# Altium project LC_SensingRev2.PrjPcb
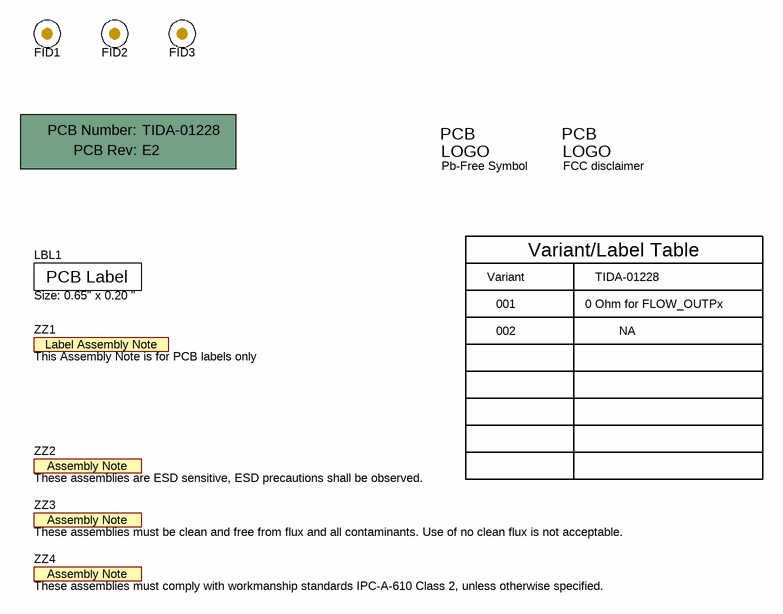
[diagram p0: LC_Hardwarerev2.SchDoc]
CopyrightYear: 2017; EVM_Orderable: NA; PCB_Layout: a0797195; PCB_Rev: E2; PRJ_Customer: Public Release; PRJ_Engineer: a0797195; PRJ_Number: TIDA-01228; PRJ_Title: LC Rotation Detection; SCH_Rev: E2; TechSupport: http://www.ti.com/support; TID: TIDA-01228
2 sheets, 61 parts. Net scope: global (net labels, ports and power ports of the same name join across sheets).
Board file: LC_Sensingrev2.PcbDoc
Sheets:
  LC_Hardwarerev2.SchDoc
  LC_PMOSrev2.SchDoc

## Sheet LC_Hardwarerev2.SchDoc
size A4; Date: Not shown in title block; ApprovedBy: Not shown in title block; CheckedBy: Not shown in title block; Author: Not shown in title block; CompanyName: Not shown in title block; DrawnBy: a0797195; Engineer: Not shown in title block; Organization: Not shown in title block; Address1: Not shown in title block; Address2: Not shown in title block; Address3: Not shown in title block; Address4: Not shown in title block; DocumentNumber: 1; Revision: Use project parameter SCH_Rev; SheetNumber: 2; SheetTotal: 2; PageSetup: Record=PageOptions¦CenterHorizontal=True¦CenterVertical=True¦PrintScale=1.00¦XCorrection=1.00¦YCorrection=1.00¦PrintKind=0¦BorderSize=5000000¦LeftOffset=0¦BottomOffset=0¦Orientation=2¦PaperLength=1000¦PaperWidth=1000¦Scale=100¦PaperSource=15¦PrintQuality=600¦MediaType=1¦DitherType=10¦PaperKind=Letter¦PrintScaleMode=1; EVM_orderable: NA

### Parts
!PCB1  Printed Circuit Board  (value not drawn)  (mechanical)
FID1  Fiducial  [Fiducial10-20]  (value not drawn)
FID2  Fiducial  [Fiducial10-20]  (value not drawn)
FID3  Fiducial  [Fiducial10-20]  (value not drawn)
LBL1  Size: 0.65" x 0.20 "  [Label_650x200]
Logo2  Pb-Free Symbol  [Pb-Free_Overlay_Small]  (no BOM)
Logo3  FCC disclaimer  [FCC_disclaimer]  (no BOM)
ZZ1  This Assembly Note is for PCB labels only  [AssemblyNoteLabel]  (no BOM)
ZZ2  These assemblies are ESD sensitive, ESD precautions shall be observed.  [AssemblyNote]  (no BOM)
ZZ3  These assemblies must be clean and free from flux and all contaminants. Use of no clean flux is not acceptable.  [AssemblyNote]  (no BOM)
ZZ4  These assemblies must comply with workmanship standards IPC-A-610 Class 2, unless otherwise specified.  [AssemblyNote]  (no BOM)

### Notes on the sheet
- Variant
- 001
- Variant/Label Table
- TIDA-01228
- 0 Ohm for FLOW_OUTPx
- 002
- NA

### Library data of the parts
!PCB1 = PCB: Manufacturer: Any; PartNumber: TIDA-01228; SymbolCreator: a0412235
FID1-FID3 = Fiducial: Fiducial mark.  There is nothing to buy or mount.; SymbolCreator: codlsc
LBL1 = THT-14-423-10: Thermal Transfer Printable Labels, 0.650" W x 0.200" H - 10,000 per roll; Manufacturer: Brady; SymbolCreator: a0412235; CompType: Label
Logo2 = Pb-Free: SymbolCreator: a0412235
Logo3 = FCC_disclaimer: SymbolCreator: codlsc
ZZ1 = AssemblyNoteLabel: SymbolCreator: a0412235
ZZ2-ZZ4 = AssemblyNote: SymbolCreator: codlsc

## Sheet LC_PMOSrev2.SchDoc: LC sensors with P-MOS FET
size A4; Date: Not shown in title block; ApprovedBy: Not shown in title block; CheckedBy: Not shown in title block; Author: Not shown in title block; CompanyName: Not shown in title block; DrawnBy: a0797195; Engineer: Not shown in title block; Organization: Not shown in title block; Address1: Not shown in title block; Address2: Not shown in title block; Address3: Not shown in title block; Address4: Not shown in title block; DocumentNumber: 1; Revision: Use project parameter SCH_Rev; SheetNumber: 1; SheetTotal: 2; PageSetup: Record=PageOptions¦CenterHorizontal=True¦CenterVertical=True¦PrintScale=1.00¦XCorrection=1.00¦YCorrection=1.00¦PrintKind=0¦BorderSize=5000000¦LeftOffset=0¦BottomOffset=0¦Orientation=2¦PaperLength=1000¦PaperWidth=1000¦Scale=100¦PaperSource=15¦PrintQuality=600¦MediaType=1¦DitherType=10¦PrintScaleMode=1¦PaperKind=Letter; EVM_orderable: NA; EVM_Rev: E2
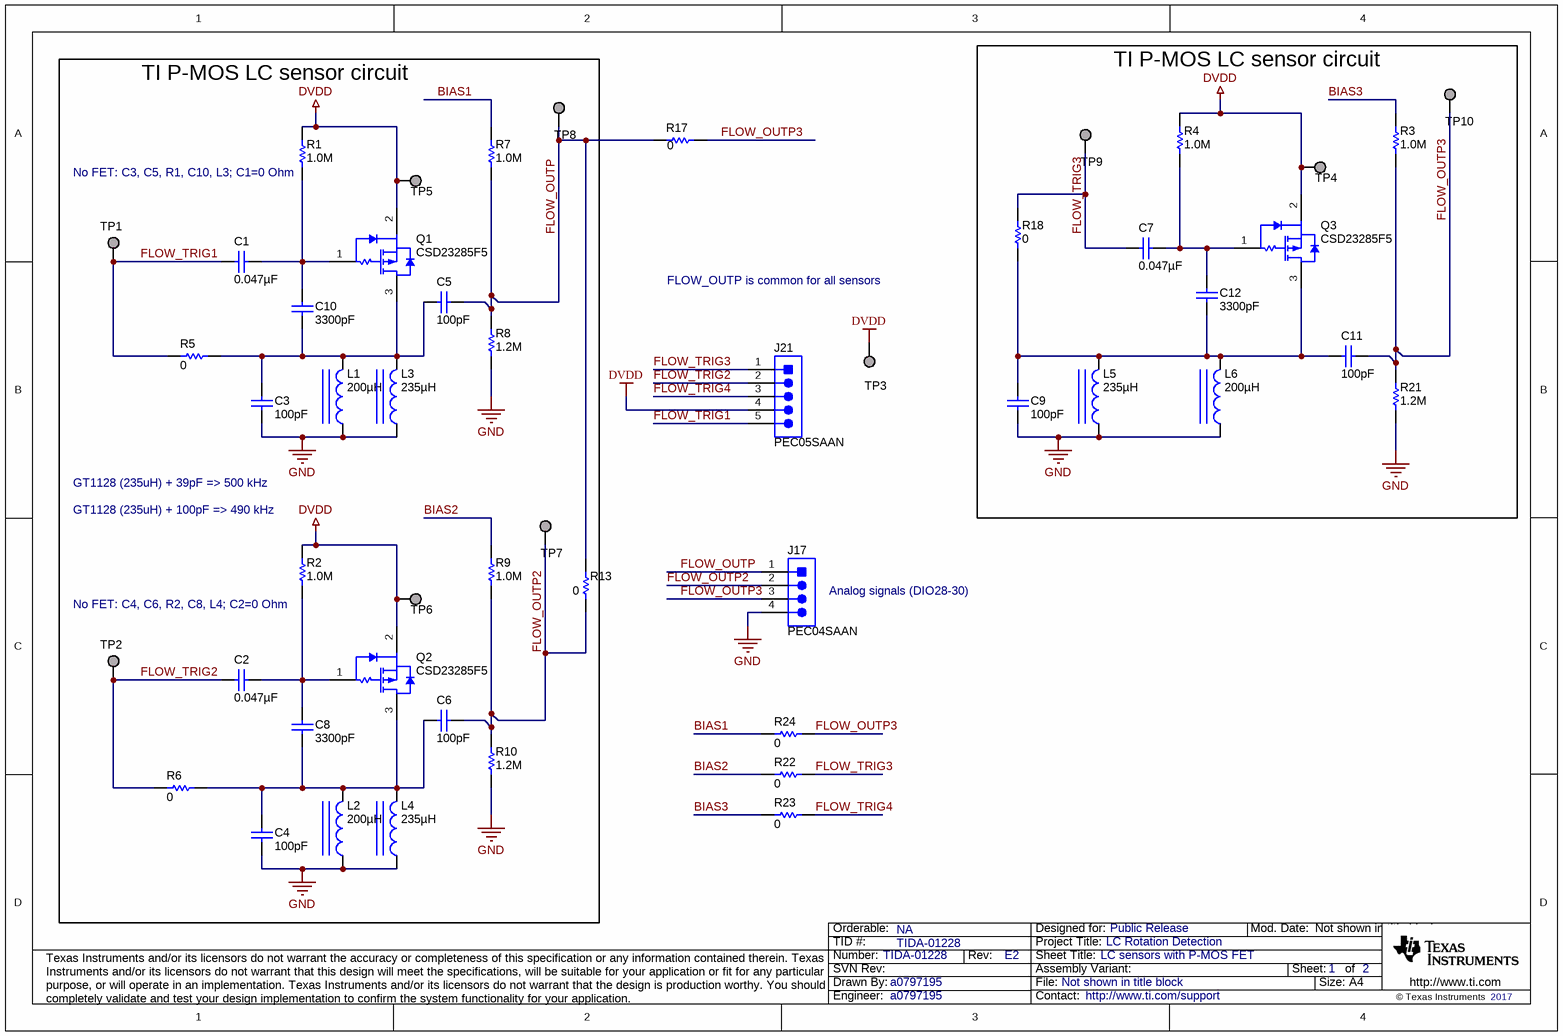
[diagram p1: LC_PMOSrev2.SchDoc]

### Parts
C1  ValueDisplayed: 0.047µF  [0402S]  (hidden comment: GRM155R61A473KA01D)
C2  ValueDisplayed: 0.047µF  [0402S]  (hidden comment: GRM155R61A473KA01D)
C3  ValueDisplayed: 100pF  [0402S]  (hidden comment: GRM1555C1H101JA01D)
C4  ValueDisplayed: 100pF  [0402S]  (hidden comment: GRM1555C1H101JA01D)
C5  ValueDisplayed: 100pF  [0402]  (hidden comment: GRM1555C1H101JA01D)
C6  ValueDisplayed: 100pF  [0402]  (hidden comment: GRM1555C1H101JA01D)
C7  ValueDisplayed: 0.047µF  [0402S]  (hidden comment: GRM155R61A473KA01D)
C8  ValueDisplayed: 3300pF  [0402]  (hidden comment: GRM155R71H332KA01D)
C9  ValueDisplayed: 100pF  [0402S]  (hidden comment: GRM1555C1H101JA01D)
C10  ValueDisplayed: 3300pF  [0402]  (hidden comment: GRM155R71H332KA01D)
C11  ValueDisplayed: 100pF  [0402]  (hidden comment: GRM1555C1H101JA01D)
C12  ValueDisplayed: 3300pF  [0402]  (hidden comment: GRM155R71H332KA01D)
J17  PEC04SAAN  [SULLINS_PEC04SAAN]
J21  PEC05SAAN  [Sullins_PxC05SAAN]
L1  ValueDisplayed: 200µH  [BV1935]  (hidden comment: BV1935)
L2  ValueDisplayed: 200µH  [BV1935]  (hidden comment: BV1935)
L3  ValueDisplayed: 235µH  [GT1128-0]  (hidden comment: GT1128-0)
L4  ValueDisplayed: 235µH  [GT1128-0]  (hidden comment: GT1128-0)
L5  ValueDisplayed: 235µH  [GT1128-0]  (hidden comment: GT1128-0)
L6  ValueDisplayed: 200µH  [BV1935]  (hidden comment: BV1935)
Q1  CSD23285F5  [YJK0003A]
Q2  CSD23285F5  [YJK0003A]
Q3  CSD23285F5  [YJK0003A]
R1  ValueDisplayed: 1.0M  [0402]  (hidden comment: CRCW04021M00JNED)
R2  ValueDisplayed: 1.0M  [0402]  (hidden comment: CRCW04021M00JNED)
R3  ValueDisplayed: 1.0M  [0402S]  (hidden comment: CRCW04021M00JNED)
R4  ValueDisplayed: 1.0M  [0402]  (hidden comment: CRCW04021M00JNED)
R5  ValueDisplayed: 0  [0402S]  (hidden comment: CRCW04020000Z0ED)
R6  ValueDisplayed: 0  [0402S]  (hidden comment: CRCW04020000Z0ED)
R7  ValueDisplayed: 1.0M  [0402S]  (hidden comment: CRCW04021M00JNED)
R8  ValueDisplayed: 1.2M  [0402S]  (hidden comment: CRCW04021M20JNED)
R9  ValueDisplayed: 1.0M  [0402S]  (hidden comment: CRCW04021M00JNED)
R10  ValueDisplayed: 1.2M  [0402S]  (hidden comment: CRCW04021M20JNED)
R13  Res_ohm: 0  [0402S]  (hidden comment: CRCW04020000Z0ED)
R17  Res_ohm: 0  [0402S]  (hidden comment: CRCW04020000Z0ED)
R18  ValueDisplayed: 0  [0402S]  (hidden comment: CRCW04020000Z0ED)
R21  ValueDisplayed: 1.2M  [0402S]  (hidden comment: CRCW04021M20JNED)
R22  ValueDisplayed: 0  [0402S]  (hidden comment: CRCW04020000Z0ED)
R23  ValueDisplayed: 0  [0402S]  (hidden comment: CRCW04020000Z0ED)
R24  ValueDisplayed: 0  [0402S]  (hidden comment: CRCW04020000Z0ED)
TP1  TP_H0.45P0.75  [TP_H045P075]  (value not drawn)  (no BOM)
TP2  TP_H0.45P0.75  [TP_H045P075]  (value not drawn)  (no BOM)
TP3  TP_H0.45P0.75  [TP_H045P075]  (value not drawn)  (no BOM)
TP4  TP_H0.45P0.75  [TP_H045P075]  (value not drawn)  (no BOM)
TP5  TP_H0.45P0.75  [TP_H045P075]  (value not drawn)  (no BOM)
TP6  TP_H0.45P0.75  [TP_H045P075]  (value not drawn)  (no BOM)
TP7  TP_H0.45P0.75  [TP_H045P075]  (value not drawn)  (no BOM)
TP8  TP_H0.45P0.75  [TP_H045P075]  (value not drawn)  (no BOM)
TP9  TP_H0.45P0.75  [TP_H045P075]  (value not drawn)  (no BOM)
TP10  TP_H0.45P0.75  [TP_H045P075]  (value not drawn)  (no BOM)

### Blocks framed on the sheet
TI P-MOS LC sensor circuit: C1-C6 C8 C10 L1-L4 Q1 Q2 R1 R2 R5-R10 R13 TP1 TP2 TP5-TP8
TI P-MOS LC sensor circuit: C7 C9 C11 C12 L5 L6 Q3 R3 R4 R18 R21 TP4 TP9 TP10

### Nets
DVDD: J21.4 Q1.2(S) Q2.2(S) Q3.2(S) R1.2 R2.2 R4.2 TP3.1 TP4.1 TP5.1 TP6.1
GND: C3.2 C4.2 C9.2 J17.4 L1.1 L2.1 L3.1 L4.1 L5.1 L6.1 R8.1 R10.1 R21.1
BIAS1: R7.2 R24.2
BIAS2: R9.2 R22.2
BIAS3: R3.2 R23.2
FLOW_OUTP: C5.1 J17.1 R7.1 R8.2 R13.1 R17.1 TP8.1
FLOW_OUTP2: C6.1 J17.2 R9.1 R10.2 R13.2 TP7.1
FLOW_OUTP3: C11.1 J17.3 R3.1 R17.2 R21.2 R24.1 TP10.1
FLOW_TRIG1: C1.2 J21.5 R5.2 TP1.1
FLOW_TRIG2: C2.2 J21.2 R6.2 TP2.1
FLOW_TRIG3: C7.2 J21.1 R18.2 R22.1 TP9.1
FLOW_TRIG4: J21.3 R23.1
NetC1_1: C1.1 C10.1 Q1.1(G) R1.1
NetC2_1: C2.1 C8.1 Q2.1(G) R2.1
NetC3_1: C3.1 C5.2 C10.2 L1.2 L3.2 Q1.3(D) R5.1
NetC4_1: C4.1 C6.2 C8.2 L2.2 L4.2 Q2.3(D) R6.1
NetC7_1: C7.1 C12.1 Q3.1(G) R4.1
NetC9_1: C9.1 C11.2 C12.2 L5.2 L6.2 Q3.3(D) R18.1

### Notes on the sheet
- (near R1) No FET: C3, C5, R1, C10, L3; C1=0 Ohm
- FLOW_OUTP is common for all sensors
- GT1128 (235uH) + 39pF => 500 kHz
- (near R2) GT1128 (235uH) + 100pF => 490 kHz
- (near R2) No FET: C4, C6, R2, C8, L4; C2=0 Ohm
- (near J17) Analog signals (DIO28-30)

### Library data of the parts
C1 C2 C7 = GRM155R61A473KA01D: CAP, CERM, 0.047 µF, 10 V, +/- 10%, X5R, 0402; Manufacturer: MuRata; Polarized: N; CompType: Capacitor; Value: 0.047uF; U/M: EA; Cap_F: 0.000000047; Tolerance_%: 10; Value1: Unknown; Value2: 10V; TaMin_C: -55; TaMax_C: 85; Cap_Case: 0402; AEC Category: Q200
C3 C4 C9 = GRM1555C1H101JA01D: CAP, CERM, 100 pF, 50 V, +/- 5%, C0G/NP0, 0402; Manufacturer: MuRata; Polarized: N; CompType: Capacitor; Value: 100pF; U/M: EA; Cap_F: 0.0000000001; Tolerance_%: 5; Value1: Unknown; VDC_V: 50; Value2: 50V; TaMin_C: -55; TaMax_C: 125; Cap_Case: 0402; AEC Category: Q200; SizeArea_mm2: 0.5; SizeAreaWB_mm2: 3; SizeX_mm: 1; SizeZ_mm: 0.6
C5 C6 C11 = GRM1555C1H101JA01D: CAP, CERM, 100 pF, 50 V, +/- 5%, C0G/NP0, 0402; Manufacturer: MuRata; Polarized: N; CompType: Capacitor; Value: 100pF; U/M: EA; Cap_F: 0.0000000001; Tolerance_%: 5; Value1: Unknown; VDC_V: 50; Value2: 50V; TaMin_C: -55; TaMax_C: 125; AEC Category: Q200; SizeArea_mm2: 0.5; SizeAreaWB_mm2: 3; SizeX_mm: 1; SizeZ_mm: 0.6
C8 C10 C12 = GRM155R71H332KA01D: CAP, CERM, 3300 pF, 50 V, +/- 10%, X7R, 0402; Manufacturer: MuRata; Polarized: N; CompType: Capacitor; Value: 3300pF; U/M: EA; Cap_F: 0.0000000033; Tolerance_%: 10; Value1: Unknown; VDC_V: 50; Value2: 50V; TaMin_C: -55; TaMax_C: 125; AEC Category: Q200; SizeArea_mm2: 0.5; SizeAreaWB_mm2: 3; SizeX_mm: 1; SizeZ_mm: 0.6
J17 = PEC04SAAN: Header, 100mil, 4x1, Tin, TH; Manufacturer: Sullins Connector Solutions; SymbolCreator: a0412235; Pitch_mm: 2.54; Gender: Male; Shrouded: N; Row_Count: 1; Current_A: 3; Voltage_V: 1800; Cert_UL: Y
J21 = PEC05SAAN: Header, 2.54mm, 5x1, Tin, TH; Manufacturer: Sullins Connector Solutions; SymbolCreator: a0412235; Pitch_mm: 2.54; Gender: Male; Shrouded: N; Row_Count: 1; Current_A: 3; Voltage_V: 1800; Cert_UL: Y
L1 L2 L6 = BV1935: Inductor, Wirewound, 200 µH, 1.9 ohm, SMD; Manufacturer: HORST DAVID GmbH; Value: 200uH; Ind_H: 200.0E-6; DCR_ohm: 1.9; Value1: 1.9 ohm; Value2: A; AEC Category: Q200; AEC Qualified: N; SizeAreaWB_mm2: 59.29; SizeArea_mm2: 32.49; SizeX_mm: 5.7; SizeZ_mm: 4.7
L3-L5 = GT1128-0: Inductor, 235µH, TH; Manufacturer: Gemphil Technologies; Value: 235uH; Ind_H: 235.0E-6; Value2: A; AEC Category: Q200; AEC Qualified: N; SizeAreaWB_mm2: 59.29; SizeArea_mm2: 32.49; SizeX_mm: 5.7; SizeZ_mm: 6.2
Q1-Q3 = CSD23285F5: MOSFET, P-CH, -12 V, -3.3 A, YJK0003A (PICOSTAR-3); Manufacturer: Texas Instruments; Alternate Manufacturer: None; SymbolCreator: a0411947; U/M: EA; ChType: P; Value: -12V; Value1: 0.035 ohm; Rdson45_ohm: 0.035; Value2: 3.2 nC; QgTyp_nC: 3.2; Vgs_V: -6; SizeAreaWB_mm2: 4.3077; SizeArea_mm2: 1.0877; SizeX_mm: 1.49; SizeY_mm: 0.73; SizeZ_mm: 0.35; AEC Category: Q101; AEC Qualified: N
R1-R4 R7 R9 = CRCW04021M00JNED: RES, 1.0 M, 5%, 0.063 W, 0402; Manufacturer: Vishay-Dale; CompType: Resistor; Value: 1.0Meg; Res_ohm: 1000000; Value_Code: 1M00; Tolerance_%: 5; Power_W: 0.063; Value2: 0.063W; VDC_V: 50; TempCo: 200 ppm/C; EIA_Code: E24; U/M: EA; AEC Category: Q200; SizeArea_mm2: 0.5; SizeX_mm: 1; SizeZ_mm: 0.6
R5 R6 R18 R22-R24 = CRCW04020000Z0ED: RES, 0, 5%, 0.063 W, 0402; Manufacturer: Vishay-Dale; CompType: Resistor; Value: 0; Value_Code: 0000; Tolerance_%: 5; Power_W: 0.063; Value2: 0.063W; VDC_V: 50; TempCo: 200 ppm/C; EIA_Code: E24; U/M: EA; AEC Category: Q200; SizeArea_mm2: 0.5; SizeX_mm: 1; SizeZ_mm: 0.6
R8 R10 R21 = CRCW04021M20JNED: RES, 1.2 M, 5%, 0.063 W, 0402; Manufacturer: Vishay-Dale; CompType: Resistor; Value: 1.2Meg; Res_ohm: 1200000; Value_Code: 1M20; Tolerance_%: 5; Power_W: 0.063; Value2: 0.063W; VDC_V: 50; TempCo: 200 ppm/C; EIA_Code: E24; U/M: EA; AEC Category: Q200
R13 R17 = CRCW04020000Z0ED: RES, 0, 5%, 0.063 W, 0402; Manufacturer: Vishay-Dale; CompType: Resistor; Value: dnp; Value_Code: 0000; Tolerance_%: 5; Power_W: 0.063; Value2: 0.063W; VDC_V: 50; TempCo: 200 ppm/C; EIA_Code: E24; U/M: EA; AEC Category: Q200
TP1-TP10 = TP_H0.45P0.75: Testpoint; Manufacturer: Texas Instruments; CompType: Pad

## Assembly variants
001: not fitted C7 C8 C9 C10 C11 C12 FID1 FID2 FID3 L1 L2 L5 L6 Q3 R3 R4 R5 R6 R7 R8 R9 R10 R13 R17 R18 R21 R22 R23 R24
No FET  LC_SensingRev2: not fitted L1 L2 L6 Q1 Q2 Q3 R3 R5 R6 R7 R8 R9 R10 R18 R21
